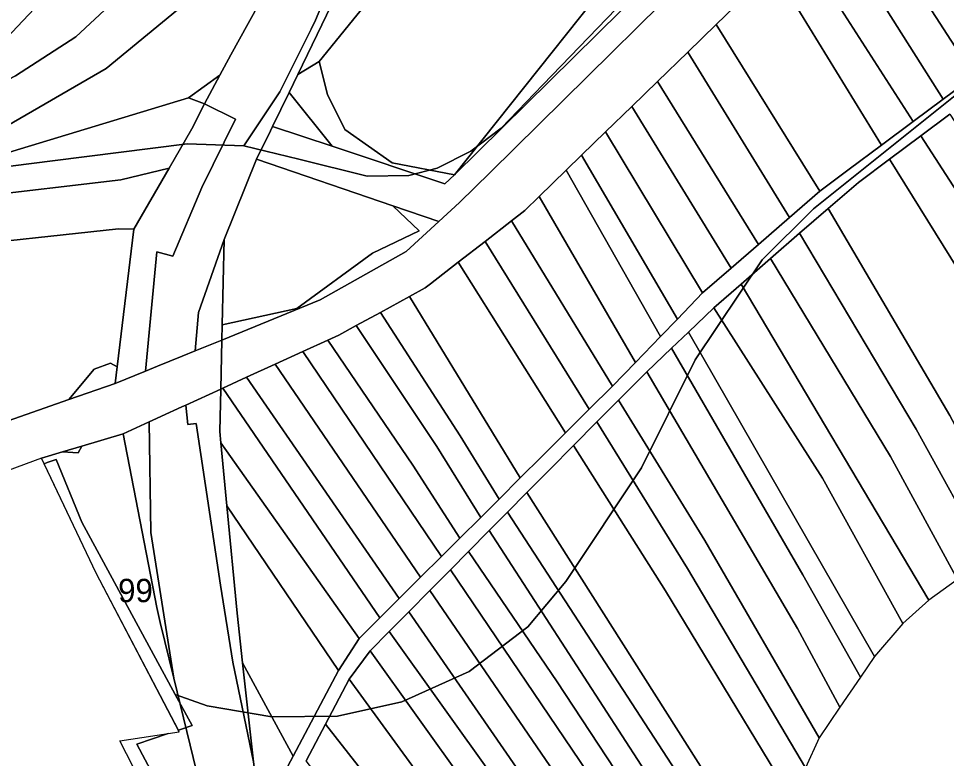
# Model space of a CAD drawing. Extents: x -535894 to -532834, y -1165802 to -1163645.
# Drawn here: x -534295.3 to -534096.6, y -1165431.5 to -1165273.1 of the extents above; entities that cross this region are included whole.
import ezdxf

# ---------------------------------------------------------------- set-up
doc = ezdxf.new("R2010")
doc.units = 0
for name, color, linetype in [('95560013', 7, 'Continuous'), ('95610013', 7, 'Continuous'), ('95630013', 7, 'Continuous'), ('95640013', 7, 'Continuous'), ('95660013', 7, 'Continuous')]:
    doc.layers.add(name, color=color, linetype=linetype)

msp = doc.modelspace()

# ---------------------------------------------------------------- linework, layer by layer
at = {"layer": '95560013'}
for points in [[(-534105.03, -1165235.88), (-534078.3, -1165276.29), (-534085.13, -1165281.37), (-534090.65, -1165285.49), (-534116.12, -1165246.09), (-534110.88, -1165241.27)], [(-534197.75, -1165241.47), (-534183.96, -1165246.08), (-534179.96, -1165247.42), (-534157.06, -1165250.17), (-534201.96, -1165306.58), (-534215.31, -1165304.06), (-534225.42, -1165296.87), (-534229.16, -1165289.39), (-534230.92, -1165282.33)], [(-534116.12, -1165246.09), (-534090.65, -1165285.49), (-534097.28, -1165290.43), (-534121.92, -1165251.44)], [(-534121.92, -1165251.44), (-534097.28, -1165290.43), (-534103.68, -1165295.19), (-534128.1, -1165257.13)], [(-534128.1, -1165257.13), (-534103.68, -1165295.19), (-534110.5, -1165300.26), (-534133.62, -1165262.47), (-534128.78, -1165257.75)], [(-534140, -1165268.66), (-534133.62, -1165262.47), (-534110.5, -1165300.26), (-534117.37, -1165305.37), (-534123.72, -1165310.1), (-534145.91, -1165274.41)], [(-534151.99, -1165280.33), (-534145.91, -1165274.41), (-534123.72, -1165310.1), (-534130.19, -1165315.73)], [(-534158.49, -1165286.65), (-534151.99, -1165280.33), (-534130.19, -1165315.73), (-534136.84, -1165321.5)], [(-534163.98, -1165291.99), (-534158.49, -1165286.65), (-534136.84, -1165321.5), (-534142.7, -1165326.58)], [(-534169.57, -1165297.42), (-534163.98, -1165291.99), (-534142.7, -1165326.58), (-534148.81, -1165331.89)], [(-534174.7, -1165302.41), (-534169.57, -1165297.42), (-534148.81, -1165331.89), (-534154.19, -1165337.49)], [(-534178, -1165305.62), (-534174.7, -1165302.41), (-534154.19, -1165337.49), (-534157.81, -1165341.24)], [(-534183.78, -1165311.24), (-534178, -1165305.62), (-534157.81, -1165341.24), (-534163.15, -1165346.78)], [(-534186.9, -1165314.27), (-534183.78, -1165311.24), (-534163.15, -1165346.78), (-534168.1, -1165351.81), (-534189.75, -1165316.48)], [(-534195.4, -1165320.86), (-534189.75, -1165316.48), (-534168.1, -1165351.81), (-534173.09, -1165356.78)], [(-534201.15, -1165325.32), (-534195.4, -1165320.86), (-534173.09, -1165356.78), (-534178.13, -1165361.8)], [(-534207.06, -1165329.91), (-534201.15, -1165325.32), (-534178.13, -1165361.8), (-534183.26, -1165366.91), (-534187.85, -1165371.47), (-534211.58, -1165332.65), (-534208.23, -1165330.82)], [(-534217.81, -1165336.04), (-534211.58, -1165332.65), (-534187.85, -1165371.47), (-534192.38, -1165376), (-534200.7, -1165362.44)], [(-534223, -1165338.87), (-534217.81, -1165336.04), (-534200.7, -1165362.44), (-534192.38, -1165376), (-534196.33, -1165379.94), (-534205.7, -1165364.73)], [(-534226.73, -1165340.9), (-534223, -1165338.87), (-534205.7, -1165364.73), (-534196.33, -1165379.94), (-534200.8, -1165384.39), (-534210.88, -1165368.77), (-534229.05, -1165341.96)], [(-534234.4, -1165344.4), (-534229.05, -1165341.96), (-534210.88, -1165368.77), (-534200.8, -1165384.39), (-534204.72, -1165388.29)], [(-534240.38, -1165347.14), (-534234.4, -1165344.4), (-534204.72, -1165388.29), (-534209.19, -1165392.73)], [(-534246.5, -1165349.94), (-534240.38, -1165347.14), (-534209.19, -1165392.73), (-534213.76, -1165397.27)]]:
    msp.add_lwpolyline(points, close=True, dxfattribs=at)
at = {"layer": '95610013'}
for points in [[(-534227.96, -1165194.63), (-534245.56, -1165220.9), (-534261.17, -1165239.42), (-534283.59, -1165262.17), (-534299.13, -1165278.61), (-534326.29, -1165293.35), (-534328.82, -1165289.63), (-534331.16, -1165286.47), (-534304.8, -1165266.72), (-534282.29, -1165235.45), (-534251.58, -1165192.19)], [(-534215.09, -1165195.97), (-534211.25, -1165196.37), (-534228.29, -1165219.76), (-534245.24, -1165239.58), (-534261.59, -1165257.06), (-534283.02, -1165277.03), (-534295.94, -1165285.41), (-534322.34, -1165299.19), (-534326.29, -1165293.35), (-534299.13, -1165278.61), (-534283.59, -1165262.17), (-534261.17, -1165239.42), (-534245.56, -1165220.9), (-534227.96, -1165194.63)], [(-534210.61, -1165196.44), (-534214.76, -1165209.81), (-534219.65, -1165224.42), (-534237.87, -1165247.3), (-534255.61, -1165266.55), (-534276.57, -1165283.84), (-534299.11, -1165296.92), (-534308.52, -1165299.61), (-534320.19, -1165302.94), (-534321.2, -1165301.18), (-534322.34, -1165299.19), (-534295.94, -1165285.41), (-534283.02, -1165277.03), (-534261.59, -1165257.06), (-534245.24, -1165239.58), (-534228.29, -1165219.76), (-534211.25, -1165196.37)], [(-534222.12, -1165231.81), (-534234.65, -1165253.49), (-534236.16, -1165256.09), (-534249.84, -1165280.89), (-534252.19, -1165285.28), (-534258.88, -1165290.11), (-534306.94, -1165304.65), (-534308.52, -1165299.61), (-534299.11, -1165296.92), (-534276.57, -1165283.84), (-534255.61, -1165266.55), (-534237.87, -1165247.3), (-534219.65, -1165224.42)], [(-534157.06, -1165250.17), (-534156.94, -1165250.18), (-534145.83, -1165251.25), (-534201.96, -1165306.58)], [(-534258.88, -1165290.11), (-534252.19, -1165285.28), (-534255.45, -1165291.38)], [(-534095.86, -1165293.64), (-534059.26, -1165349.61), (-534052.73, -1165363.08), (-534059.04, -1165367.66), (-534069.65, -1165348.37), (-534102.06, -1165298.25)], [(-534102.06, -1165298.25), (-534069.65, -1165348.37), (-534059.04, -1165367.66), (-534067.65, -1165373.91), (-534079.55, -1165350.17), (-534108.76, -1165303.24)], [(-534108.76, -1165303.24), (-534079.55, -1165350.17), (-534067.65, -1165373.91), (-534075.22, -1165379.41), (-534081.89, -1165384.25), (-534095.85, -1165358.13), (-534121.89, -1165313.8), (-534115.44, -1165308.22)], [(-534128.01, -1165319.11), (-534121.89, -1165313.8), (-534095.85, -1165358.13), (-534081.89, -1165384.25), (-534087.82, -1165388.56), (-534103.02, -1165361.05)], [(-534134.26, -1165324.52), (-534128.01, -1165319.11), (-534103.02, -1165361.05), (-534087.82, -1165388.56), (-534094.23, -1165393.22), (-534108.57, -1165366.89)], [(-534140.55, -1165329.98), (-534134.26, -1165324.52), (-534108.57, -1165366.89), (-534094.23, -1165393.22), (-534100.32, -1165397.66)], [(-534146.4, -1165335.06), (-534140.55, -1165329.98), (-534100.32, -1165397.66), (-534105.93, -1165402.64), (-534123.09, -1165371.57)], [(-534151.85, -1165340.25), (-534146.4, -1165335.06), (-534123.09, -1165371.57), (-534105.93, -1165402.64), (-534112, -1165409.73)], [(-534155.49, -1165343.73), (-534151.85, -1165340.25), (-534112, -1165409.73), (-534115, -1165414.12), (-534127.3, -1165392.23)], [(-534160.76, -1165348.75), (-534155.49, -1165343.73), (-534127.3, -1165392.23), (-534115, -1165414.12), (-534119.41, -1165420.59), (-534128.46, -1165403.74)], [(-534251.58, -1165352.26), (-534246.5, -1165349.94), (-534213.76, -1165397.27), (-534217.91, -1165401.41)], [(-534166.84, -1165354.83), (-534160.76, -1165348.75), (-534128.46, -1165403.74), (-534119.41, -1165420.59), (-534123.86, -1165427.13), (-534148.33, -1165384.9)], [(-534252.01, -1165352.47), (-534251.58, -1165352.26), (-534217.91, -1165401.41), (-534222.38, -1165405.86), (-534251.99, -1165363.99), (-534252.23, -1165361.54)], [(-534171.44, -1165359.48), (-534166.84, -1165354.83), (-534148.33, -1165384.9), (-534123.86, -1165427.13), (-534126.75, -1165433.55), (-534152.03, -1165390.89)], [(-534176.44, -1165364.53), (-534171.44, -1165359.48), (-534152.03, -1165390.89), (-534126.75, -1165433.55), (-534129.01, -1165441.31), (-534156.72, -1165395.63)], [(-534250.69, -1165377.47), (-534251.99, -1165363.99), (-534222.38, -1165405.86), (-534226.8, -1165412.68)], [(-534181.53, -1165369.66), (-534176.44, -1165364.53), (-534156.72, -1165395.63), (-534129.01, -1165441.31), (-534131.39, -1165449.51), (-534133.74, -1165457.61), (-534186.43, -1165374.61)], [(-534190.57, -1165378.79), (-534186.43, -1165374.61), (-534133.74, -1165457.61), (-534135.45, -1165463.49)], [(-534194.5, -1165382.75), (-534190.57, -1165378.79), (-534135.45, -1165463.49), (-534137.53, -1165470.62)], [(-534198.92, -1165387.21), (-534194.5, -1165382.75), (-534137.53, -1165470.62), (-534139.34, -1165476.85), (-534179.96, -1165415.17)], [(-534202.8, -1165391.13), (-534198.92, -1165387.21), (-534179.96, -1165415.17), (-534139.34, -1165476.85), (-534140.98, -1165482.5)], [(-534207.22, -1165395.6), (-534202.8, -1165391.13), (-534140.98, -1165482.5), (-534142.99, -1165489.42)], [(-534211.75, -1165400.17), (-534207.22, -1165395.6), (-534142.99, -1165489.42), (-534144.9, -1165495.99), (-534170.58, -1165458.63), (-534182.69, -1165442.19)], [(-534215.9, -1165404.37), (-534211.75, -1165400.17), (-534182.69, -1165442.19), (-534170.58, -1165458.63), (-534144.9, -1165495.99), (-534146.71, -1165502.23), (-534170.82, -1165467.44)], [(-534220.02, -1165408.52), (-534215.9, -1165404.37), (-534170.82, -1165467.44), (-534146.71, -1165502.23), (-534148.5, -1165508.42)], [(-534224.52, -1165414.59), (-534220.02, -1165408.52), (-534148.5, -1165508.42), (-534150.66, -1165515.85)], [(-534229.56, -1165424.19), (-534224.52, -1165414.59), (-534150.66, -1165515.85), (-534153.04, -1165524.07), (-534181.38, -1165485.61)], [(-534233.69, -1165432.05), (-534229.56, -1165424.19), (-534181.38, -1165485.61), (-534153.04, -1165524.07), (-534155.94, -1165534.08), (-534184.87, -1165495.38)]]:
    msp.add_lwpolyline(points, close=True, dxfattribs=at)
at = {"layer": '95630013'}
for points in [[(-534140, -1165268.66), (-534145.91, -1165274.41), (-534151.99, -1165280.33), (-534158.49, -1165286.65), (-534163.98, -1165291.99), (-534169.57, -1165297.42), (-534174.7, -1165302.41), (-534178, -1165305.62), (-534183.78, -1165311.24), (-534186.9, -1165314.27), (-534189.75, -1165316.48), (-534195.4, -1165320.86), (-534201.15, -1165325.32), (-534207.06, -1165329.91), (-534208.23, -1165330.82), (-534211.58, -1165332.65), (-534217.81, -1165336.04), (-534223, -1165338.87), (-534226.73, -1165340.9), (-534229.05, -1165341.96), (-534234.4, -1165344.4), (-534240.38, -1165347.14), (-534246.5, -1165349.94), (-534251.58, -1165352.26), (-534252.01, -1165352.47), (-534251.77, -1165341.96), (-534230.69, -1165333.38), (-534212.27, -1165323.02), (-534205.31, -1165316.61), (-534200.89, -1165312.54), (-534194.29, -1165306.12), (-534136.8, -1165249.37)], [(-534300.23, -1165360.21), (-534284.53, -1165354.73), (-534274.64, -1165351.27), (-534268.13, -1165348.62), (-534265.54, -1165347.57), (-534260.27, -1165345.42), (-534257.49, -1165344.29), (-534251.77, -1165341.96), (-534252.01, -1165352.47), (-534259.48, -1165355.88), (-534260.34, -1165356.27), (-534264.71, -1165358.28), (-534265.74, -1165358.75), (-534267.32, -1165359.47), (-534272.9, -1165362.02), (-534281.74, -1165364.67), (-534285.88, -1165365.91), (-534290.38, -1165367.27), (-534311.13, -1165374.91)]]:
    msp.add_lwpolyline(points, dxfattribs=at)
at = {"layer": '95640013'}
for points in [[(-534066.72, -1165179.82), (-534136.8, -1165249.37), (-534194.29, -1165306.12), (-534200.89, -1165312.54), (-534205.31, -1165316.61), (-534215.14, -1165313.24), (-534244.31, -1165303.28), (-534241.33, -1165297.17), (-534240.88, -1165296.25), (-534228.15, -1165300.5), (-534203.98, -1165308.56), (-534201.96, -1165306.58), (-534145.83, -1165251.25), (-534131.84, -1165237.61), (-534110.19, -1165216.6), (-534097.29, -1165204.09), (-534078.91, -1165185.19), (-534077.66, -1165183.91)], [(-534225.18, -1165263.79), (-534235.49, -1165285.14), (-534237.36, -1165289.01), (-534240.88, -1165296.25), (-534241.33, -1165297.17), (-534244.31, -1165303.28), (-534251.27, -1165320.44), (-534256.77, -1165336.1), (-534257.49, -1165344.29), (-534260.27, -1165345.42), (-534265.54, -1165347.57), (-534268.13, -1165348.62), (-534265.69, -1165323.08), (-534262.28, -1165324.03), (-534256.03, -1165309.32), (-534248.87, -1165294.69), (-534255.45, -1165291.38), (-534252.19, -1165285.28), (-534249.84, -1165280.89), (-534236.16, -1165256.09)], [(-534243.4, -1165444.03), (-534236.52, -1165431.02), (-534226.8, -1165412.68), (-534222.38, -1165405.86), (-534217.91, -1165401.41), (-534213.76, -1165397.27), (-534209.19, -1165392.73), (-534204.72, -1165388.29), (-534200.8, -1165384.39), (-534196.33, -1165379.94), (-534192.38, -1165376), (-534187.85, -1165371.47), (-534183.26, -1165366.91), (-534178.13, -1165361.8), (-534173.09, -1165356.78), (-534168.1, -1165351.81), (-534163.15, -1165346.78), (-534157.81, -1165341.24), (-534154.19, -1165337.49), (-534148.81, -1165331.89), (-534142.7, -1165326.58), (-534136.84, -1165321.5), (-534130.19, -1165315.73), (-534123.72, -1165310.1), (-534117.37, -1165305.37), (-534110.5, -1165300.26), (-534103.68, -1165295.19), (-534097.28, -1165290.43), (-534090.65, -1165285.49)], [(-534306.94, -1165304.65), (-534258.88, -1165290.11), (-534255.45, -1165291.38), (-534258.18, -1165296.74), (-534263.07, -1165305.2), (-534273.43, -1165307.68), (-534336.76, -1165315.12)], [(-534095.86, -1165293.64), (-534102.06, -1165298.25), (-534108.76, -1165303.24), (-534115.44, -1165308.22), (-534121.89, -1165313.8), (-534128.01, -1165319.11), (-534134.26, -1165324.52), (-534140.55, -1165329.98), (-534146.4, -1165335.06), (-534151.85, -1165340.25), (-534155.49, -1165343.73), (-534160.76, -1165348.75), (-534166.84, -1165354.83), (-534171.44, -1165359.48), (-534176.44, -1165364.53), (-534181.53, -1165369.66), (-534186.43, -1165374.61), (-534190.57, -1165378.79), (-534194.5, -1165382.75), (-534198.92, -1165387.21), (-534202.8, -1165391.13), (-534207.22, -1165395.6), (-534211.75, -1165400.17), (-534215.9, -1165404.37), (-534220.02, -1165408.52), (-534224.52, -1165414.59), (-534229.56, -1165424.19), (-534233.69, -1165432.05)], [(-534551.38, -1165379.05), (-534422.4, -1165326.53), (-534364.57, -1165315.97), (-534336.76, -1165315.12), (-534273.43, -1165307.68), (-534263.07, -1165305.2), (-534270.61, -1165318.24), (-534273.89, -1165318.16), (-534312.18, -1165322.29), (-534336.67, -1165324.94), (-534360.45, -1165326.25), (-534364.65, -1165326.48), (-534419.17, -1165333.25), (-534502.24, -1165366.65)]]:
    msp.add_lwpolyline(points, dxfattribs=at)
for points in [[(-534185.07, -1165211.45), (-534178.75, -1165211.76), (-534197.75, -1165241.47), (-534230.92, -1165282.33), (-534235.49, -1165285.14), (-534225.18, -1165263.79), (-534220.39, -1165254.46), (-534198.6, -1165228.24)], [(-534235.49, -1165285.14), (-534230.92, -1165282.33), (-534229.16, -1165289.39), (-534225.42, -1165296.87), (-534215.31, -1165304.06), (-534201.96, -1165306.58), (-534203.98, -1165308.56), (-534228.15, -1165300.5), (-534237.36, -1165289.01)], [(-534240.88, -1165296.25), (-534237.36, -1165289.01), (-534228.15, -1165300.5)], [(-534248.87, -1165294.69), (-534256.03, -1165309.32), (-534262.28, -1165324.03), (-534265.69, -1165323.08), (-534268.13, -1165348.62), (-534274.64, -1165351.27), (-534274.2, -1165347.69), (-534270.61, -1165318.24), (-534263.07, -1165305.2), (-534258.18, -1165296.74), (-534255.45, -1165291.38)], [(-534215.14, -1165313.24), (-534209.48, -1165318.59), (-534219.52, -1165323.38), (-534235.68, -1165335.21), (-534251.69, -1165338.72), (-534251.27, -1165320.44), (-534244.31, -1165303.28)], [(-534205.31, -1165316.61), (-534212.27, -1165323.02), (-534230.69, -1165333.38), (-534251.77, -1165341.96), (-534251.69, -1165338.72), (-534235.68, -1165335.21), (-534219.52, -1165323.38), (-534209.48, -1165318.59), (-534215.14, -1165313.24)], [(-534273.89, -1165318.16), (-534270.61, -1165318.24), (-534274.2, -1165347.69), (-534275.59, -1165346.89), (-534279.12, -1165348.18), (-534284.53, -1165354.73), (-534300.23, -1165360.21), (-534301.65, -1165360.47), (-534307.88, -1165340.19), (-534312.18, -1165322.29)], [(-534256.77, -1165336.1), (-534251.27, -1165320.44), (-534251.69, -1165338.72), (-534251.77, -1165341.96), (-534257.49, -1165344.29)], [(-534275.59, -1165346.89), (-534274.2, -1165347.69), (-534274.64, -1165351.27), (-534284.53, -1165354.73), (-534279.12, -1165348.18)], [(-534259.48, -1165355.88), (-534252.01, -1165352.47), (-534252.23, -1165361.54), (-534251.99, -1165363.99), (-534250.69, -1165377.47), (-534248.48, -1165400.41), (-534247.31, -1165411.07), (-534244.98, -1165432.27), (-534249.38, -1165410.91), (-534252.04, -1165394.43), (-534257.28, -1165359.81), (-534259.04, -1165360.05)], [(-534260.34, -1165356.27), (-534259.48, -1165355.88), (-534259.04, -1165360.05), (-534257.28, -1165359.81), (-534252.04, -1165394.43), (-534249.38, -1165410.91), (-534244.98, -1165432.27), (-534243.4, -1165444.03), (-534242.7, -1165449.22), (-534241.22, -1165460.36), (-534234.3, -1165490.14), (-534242.12, -1165462.96), (-534244.14, -1165462.64), (-534249.66, -1165461.74), (-534253.34, -1165461.15), (-534257.19, -1165434.29), (-534262.04, -1165414.36), (-534266.94, -1165383.2), (-534267.32, -1165359.47), (-534265.74, -1165358.75), (-534264.71, -1165358.28)], [(-534272.9, -1165362.02), (-534267.32, -1165359.47), (-534266.94, -1165383.2), (-534262.04, -1165414.36), (-534264.94, -1165402.42), (-534265.72, -1165399.2)], [(-534272.9, -1165362.02), (-534265.72, -1165399.2), (-534264.94, -1165402.42), (-534262.04, -1165414.36), (-534257.19, -1165434.29), (-534253.34, -1165461.15), (-534256.73, -1165460.61), (-534273.58, -1165427.79), (-534260.88, -1165425.85), (-534278.69, -1165391.9), (-534290.38, -1165367.27), (-534285.88, -1165365.91), (-534282.54, -1165366.1), (-534281.74, -1165364.67)], [(-534281.74, -1165364.67), (-534282.54, -1165366.1), (-534285.88, -1165365.91)], [(-534248.48, -1165400.41), (-534250.69, -1165377.47), (-534226.8, -1165412.68), (-534236.52, -1165431.02), (-534247.31, -1165411.07)], [(-534247.31, -1165411.07), (-534236.52, -1165431.02), (-534243.4, -1165444.03), (-534244.98, -1165432.27)]]:
    msp.add_lwpolyline(points, close=True, dxfattribs=at)
at = {"layer": '95660013'}
for points in [[(-534504, -1165364.91), (-534479.15, -1165348.82), (-534459.071, -1165335.819), (-534440.92, -1165327.96), (-534400.789, -1165317.92), (-534366.86, -1165313.619), (-534340.91, -1165310.331), (-534288.01, -1165303.627), (-534259.201, -1165299.977), (-534247.08, -1165300.4), (-534235.298, -1165303.278), (-534220.661, -1165306.853), (-534211.72, -1165306.77), (-534205.67, -1165305.18), (-534198.42, -1165301.519), (-534191.96, -1165296.599), (-534183.05, -1165287.34), (-534159.56, -1165262.93), (-534128.66, -1165234.701), (-534052.52, -1165160.48), (-533990.56, -1165093.1), (-533942.78, -1165048.02)], [(-534215.59, -1165178.943), (-534214.43, -1165186.48), (-534210.92, -1165193.25), (-534208.85, -1165204), (-534209.25, -1165212.04), (-534210.291, -1165218.89), (-534213.95, -1165231.16), (-534231.71, -1165273.52), (-534232.654, -1165275.407), (-534239.36, -1165288.81), (-534247.08, -1165300.4), (-534259.201, -1165299.977), (-534288.01, -1165303.627), (-534340.91, -1165310.331)], [(-534159.56, -1165262.93), (-534183.05, -1165287.34), (-534191.96, -1165296.599), (-534198.42, -1165301.519), (-534205.67, -1165305.18), (-534211.72, -1165306.77), (-534220.661, -1165306.853), (-534235.298, -1165303.278), (-534247.08, -1165300.4), (-534239.36, -1165288.81), (-534232.654, -1165275.407), (-534231.71, -1165273.52), (-534213.95, -1165231.16)], [(-533928.089, -1165275.274), (-533943.99, -1165283.5), (-533974.66, -1165305.36), (-534013.02, -1165333.89), (-534079.092, -1165382.22), (-534081.89, -1165384.25), (-534087.82, -1165388.56), (-534094.23, -1165393.22), (-534100.32, -1165397.66), (-534105.93, -1165402.64), (-534112, -1165409.73), (-534115, -1165414.12), (-534119.41, -1165420.59), (-534123.86, -1165427.13), (-534126.75, -1165433.55)], [(-534079.332, -1165277.377), (-534105.4, -1165298.17), (-534125.07, -1165313.86), (-534136.06, -1165324.773), (-534150.4, -1165346.2), (-534161.87, -1165369.29), (-534178.11, -1165393.66), (-534186.226, -1165403.375), (-534198.82, -1165412.93), (-534213.249, -1165419.389), (-534226.966, -1165422.497), (-534241.03, -1165422.65), (-534254.891, -1165420.26), (-534261.74, -1165417.867), (-534281.75, -1165380.99), (-534287.26, -1165367.54), (-534289.197, -1165368.215), (-534289.827, -1165368.435), (-534290.38, -1165367.27), (-534311.13, -1165374.91)], [(-534254.02, -1165458.36), (-534270, -1165428.46), (-534263.286, -1165426.218), (-534260.88, -1165425.85), (-534261.074, -1165425.479), (-534260.433, -1165425.265), (-534258.14, -1165424.5), (-534261.74, -1165417.867), (-534254.891, -1165420.26), (-534241.03, -1165422.65), (-534226.966, -1165422.497), (-534213.249, -1165419.389), (-534198.82, -1165412.93), (-534186.226, -1165403.375), (-534178.11, -1165393.66), (-534161.87, -1165369.29), (-534150.4, -1165346.2), (-534136.06, -1165324.773), (-534125.07, -1165313.86), (-534105.4, -1165298.17), (-534079.332, -1165277.377)]]:
    msp.add_lwpolyline(points, dxfattribs=at)
for points in [[(-534260.433, -1165425.265), (-534261.074, -1165425.479), (-534278.69, -1165391.9), (-534289.827, -1165368.435), (-534289.197, -1165368.215), (-534287.26, -1165367.54), (-534281.75, -1165380.99), (-534261.74, -1165417.867), (-534258.14, -1165424.5)], [(-534221.041, -1165492.816), (-534221.281, -1165493.132), (-534234.3, -1165490.14), (-534242.12, -1165462.96), (-534244.14, -1165462.64), (-534249.66, -1165461.74), (-534253.34, -1165461.15), (-534256.73, -1165460.61), (-534273.58, -1165427.79), (-534263.286, -1165426.218), (-534270, -1165428.46), (-534254.02, -1165458.36), (-534247.37, -1165459.96), (-534241.8, -1165460.84), (-534239.62, -1165461.22), (-534239.05, -1165464.37), (-534233.37, -1165489.25), (-534231.05, -1165489.74), (-534220.2, -1165491.71)]]:
    msp.add_lwpolyline(points, close=True, dxfattribs=at)

# ---------------------------------------------------------------- texts
msp.add_text('99', height=5, rotation=0, dxfattribs=at).set_placement((-534273.984, -1165398.087))

doc.saveas('drawing.dxf')
